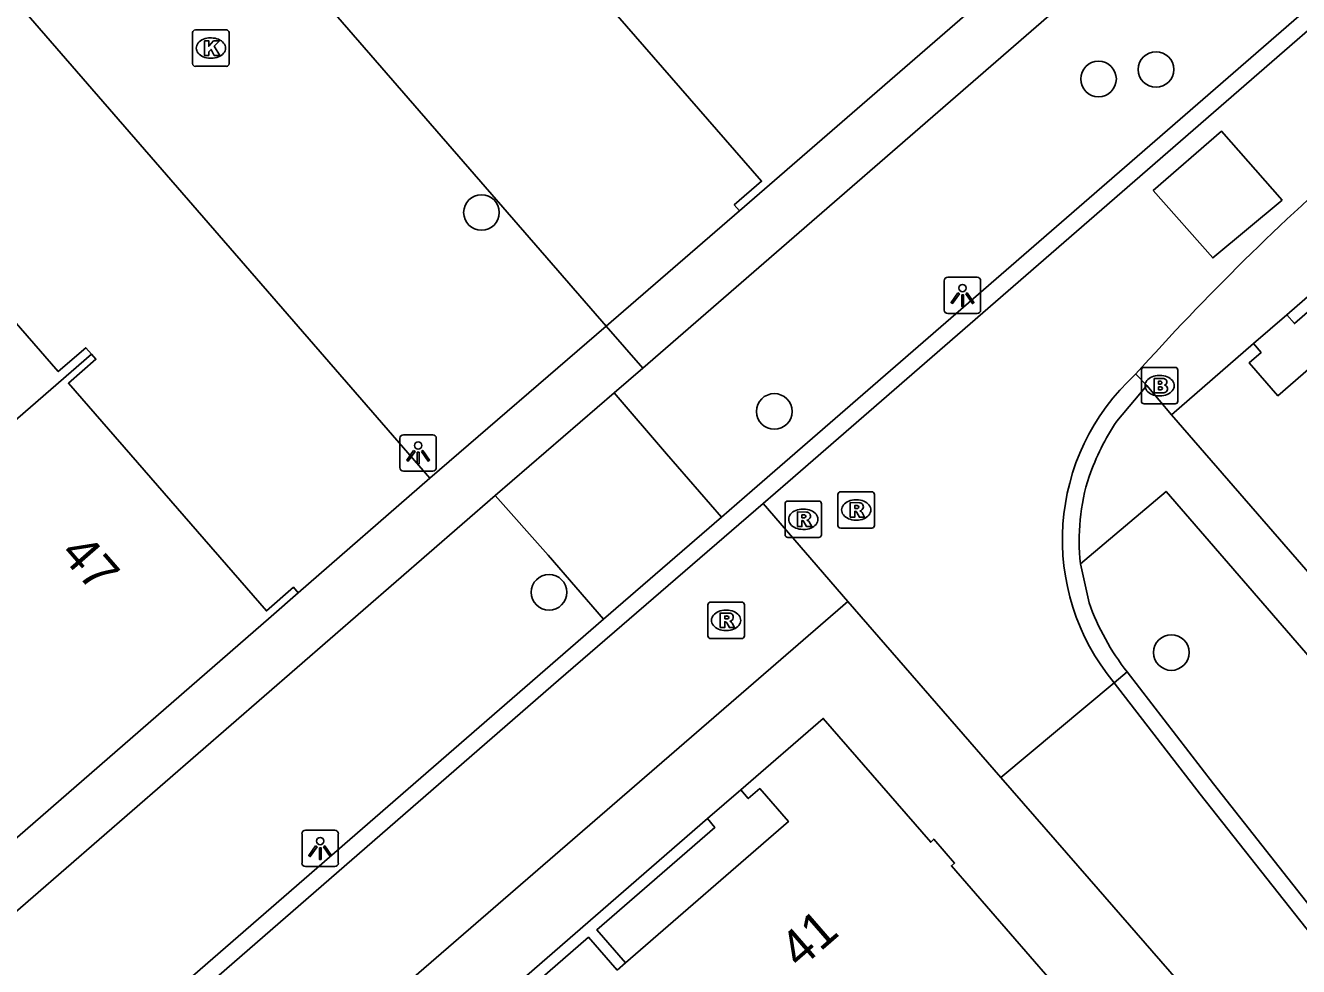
# Model space of a CAD drawing. Extents: x 155888 to 156864, y 383882 to 384671.
# Drawn here: x 156470.82 to 156505.75, y 384184.97 to 384210.79 of the extents above; entities that cross this region are included whole.
import ezdxf

# ---------------------------------------------------------------- set-up
doc = ezdxf.new("R2010")
doc.units = 0
for name, color, linetype in [('IMGEO_Boom', 7, 'Continuous'), ('IMGEO_Brandkraan', 7, 'Continuous'), ('IMGEO_Kolk', 7, 'Continuous'), ('IMGEO_Lichtpunt', 7, 'Continuous'), ('IMGEO_Muur', 7, 'Continuous'), ('IMGEO_Pand', 7, 'Continuous'), ('IMGEO_Pand_nummerreeks', 7, 'Continuous'), ('IMGEO_Rijbaan_lokaal_gesloten', 7, 'Continuous'), ('IMGEO_Rijbaan_lokaal_open', 7, 'Continuous'), ('IMGEO_Rioolput', 7, 'Continuous'), ('IMGEO_Voetpad_open', 7, 'Continuous')]:
    doc.layers.add(name, color=color, linetype=linetype)

msp = doc.modelspace()

# ---------------------------------------------------------------- linework, layer by layer
at = {"layer": 'IMGEO_Boom'}
for centre in [(156500.259, 384209.32), (156501.836, 384209.58), (156483.328, 384205.656), (156491.362, 384200.197), (156485.182, 384195.235), (156502.256, 384193.581)]:
    msp.add_circle(centre, 0.489, dxfattribs=at)
at = {"layer": 'IMGEO_Brandkraan'}
for p, q in [((156501.509, 384201.405), (156502.361, 384201.405)), ((156501.434, 384200.479), (156501.434, 384201.331)), ((156501.922, 384201.185), (156501.947, 384201.185)), ((156502.435, 384201.331), (156502.435, 384200.479)), ((156502.361, 384200.405), (156501.509, 384200.405)), ((156501.945, 384200.625), (156501.92, 384200.625))]:
    msp.add_line(p, q, dxfattribs=at)
for points in [[(156501.509, 384201.405), (156502.361, 384201.405)], [(156501.434, 384200.479), (156501.434, 384201.331)], [(156501.782, 384201.105), (156501.782, 384200.705), (156501.995, 384200.705)], [(156502.013, 384201.105), (156501.782, 384201.105)], [(156502.435, 384201.331), (156502.435, 384200.479)], [(156501.961, 384201.024), (156501.907, 384201.024), (156501.907, 384200.948)], [(156501.907, 384200.948), (156501.96, 384200.948)], [(156501.969, 384200.872), (156501.907, 384200.872), (156501.907, 384200.791)], [(156501.907, 384200.791), (156501.969, 384200.791)], [(156502.361, 384200.405), (156501.509, 384200.405)]]:
    msp.add_lwpolyline(points, dxfattribs=at)
for centre, radius, start, end in [((156501.511, 384201.329), 0.0765, 91.552, 178.448), ((156501.511, 384201.329), 0.0765, 91.552, 178.448), ((156502.359, 384201.329), 0.0765, 1.552, 88.448), ((156502.359, 384201.329), 0.0765, 1.552, 88.448), ((156502.017, 384200.96), 0.145, 59.4692, 91.5367), ((156502.042, 384201.007), 0.0922, 285.5137, 58.1501), ((156501.962, 384200.986), 0.0379, 267.8285, 90.9355), ((156501.97, 384200.831), 0.0404, 269.8759, 90.5077), ((156502.001, 384200.956), 0.251, 268.6676, 293.5347), ((156502.047, 384200.815), 0.105, 301.3115, 78.989), ((156501.511, 384200.481), 0.0765, 181.552, 268.448), ((156501.511, 384200.481), 0.0765, 181.552, 268.448), ((156502.359, 384200.481), 0.0765, 271.552, 358.448), ((156502.359, 384200.481), 0.0765, 271.552, 358.448)]:
    msp.add_arc(centre, radius, start, end, dxfattribs=at)
for centre, major_axis, ratio, start_param, end_param in [((156501.921, 384200.905), (-0.387, 0.002), 0.722429, 4.712389, 7.853982), ((156501.946, 384200.905), (-0.39, 0.002), 0.717154, 1.570796, 4.712389)]:
    msp.add_ellipse(centre, major_axis=major_axis, ratio=ratio, start_param=start_param, end_param=end_param, dxfattribs=at)
at = {"layer": 'IMGEO_Kolk'}
for p, q in [((156475.403, 384209.741), (156475.403, 384210.593)), ((156475.478, 384210.667), (156476.33, 384210.667)), ((156476.404, 384210.593), (156476.404, 384209.741)), ((156475.891, 384210.447), (156475.916, 384210.447)), ((156475.914, 384209.887), (156475.889, 384209.887)), ((156476.33, 384209.667), (156475.478, 384209.667))]:
    msp.add_line(p, q, dxfattribs=at)
for points in [[(156475.403, 384209.741), (156475.403, 384210.593)], [(156475.478, 384210.667), (156476.33, 384210.667)], [(156476.404, 384210.593), (156476.404, 384209.741)], [(156475.724, 384210.367), (156475.847, 384210.367), (156475.847, 384210.216), (156475.977, 384210.367), (156476.141, 384210.367), (156475.995, 384210.216), (156476.148, 384209.967), (156475.996, 384209.967), (156475.911, 384210.131), (156475.847, 384210.064), (156475.847, 384209.967), (156475.724, 384209.967), (156475.724, 384210.367)], [(156476.33, 384209.667), (156475.478, 384209.667)]]:
    msp.add_lwpolyline(points, dxfattribs=at)
for centre, start, end in [((156475.48, 384210.591), 91.552, 178.448), ((156475.48, 384210.591), 91.552, 178.448), ((156476.328, 384210.591), 1.552, 88.448), ((156476.328, 384210.591), 1.552, 88.448), ((156475.48, 384209.743), 181.552, 268.448), ((156475.48, 384209.743), 181.552, 268.448), ((156476.328, 384209.743), 271.552, 358.448), ((156476.328, 384209.743), 271.552, 358.448)]:
    msp.add_arc(centre, 0.0765, start, end, dxfattribs=at)
for centre, major_axis, ratio, start_param, end_param in [((156475.89, 384210.167), (-0.387, 0.002), 0.722429, 4.712389, 7.853982), ((156475.915, 384210.167), (-0.39, 0.002), 0.717154, 1.570796, 4.712389)]:
    msp.add_ellipse(centre, major_axis=major_axis, ratio=ratio, start_param=start_param, end_param=end_param, dxfattribs=at)
at = {"layer": 'IMGEO_Lichtpunt'}
for p, q in [((156496.93, 384203.88), (156496.122, 384203.88)), ((156496.93, 384203.88), (156496.122, 384203.88)), ((156496.028, 384203.785), (156496.028, 384202.978)), ((156496.028, 384203.785), (156496.028, 384202.978)), ((156497.024, 384202.978), (156497.024, 384203.785)), ((156497.024, 384202.978), (156497.024, 384203.785)), ((156496.122, 384202.884), (156496.93, 384202.884)), ((156496.122, 384202.884), (156496.93, 384202.884)), ((156481.092, 384199.463), (156481.092, 384198.656)), ((156481.092, 384199.463), (156481.092, 384198.656)), ((156481.994, 384199.558), (156481.186, 384199.558)), ((156481.994, 384199.558), (156481.186, 384199.558)), ((156482.088, 384198.656), (156482.088, 384199.463)), ((156482.088, 384198.656), (156482.088, 384199.463)), ((156481.186, 384198.562), (156481.994, 384198.562)), ((156481.186, 384198.562), (156481.994, 384198.562)), ((156478.404, 384188.61), (156478.404, 384187.803)), ((156478.404, 384188.61), (156478.404, 384187.803)), ((156479.306, 384188.705), (156478.498, 384188.705)), ((156479.306, 384188.705), (156478.498, 384188.705)), ((156479.4, 384187.803), (156479.4, 384188.61)), ((156479.4, 384187.803), (156479.4, 384188.61)), ((156478.498, 384187.709), (156479.306, 384187.709)), ((156478.498, 384187.709), (156479.306, 384187.709))]:
    msp.add_line(p, q, dxfattribs=at)
for points in [[(156496.402, 384203.449), (156496.441, 384203.421), (156496.253, 384203.159), (156496.215, 384203.186), (156496.402, 384203.449)], [(156496.504, 384203.401), (156496.551, 384203.401), (156496.551, 384203.079), (156496.504, 384203.079), (156496.504, 384203.401)], [(156496.614, 384203.421), (156496.652, 384203.448), (156496.839, 384203.186), (156496.8, 384203.158), (156496.614, 384203.421)], [(156481.466, 384199.127), (156481.505, 384199.099), (156481.317, 384198.837), (156481.279, 384198.864), (156481.466, 384199.127)], [(156481.568, 384199.079), (156481.615, 384199.079), (156481.615, 384198.757), (156481.568, 384198.757), (156481.568, 384199.079)], [(156481.678, 384199.099), (156481.716, 384199.126), (156481.903, 384198.864), (156481.864, 384198.836), (156481.678, 384199.099)], [(156478.778, 384188.274), (156478.817, 384188.246), (156478.629, 384187.984), (156478.591, 384188.011), (156478.778, 384188.274)], [(156478.88, 384188.226), (156478.927, 384188.226), (156478.927, 384187.904), (156478.88, 384187.904), (156478.88, 384188.226)], [(156478.99, 384188.246), (156479.028, 384188.273), (156479.215, 384188.011), (156479.176, 384187.983), (156478.99, 384188.246)]]:
    msp.add_lwpolyline(points, dxfattribs=at)
for centre in [(156496.527, 384203.583), (156481.591, 384199.261), (156478.903, 384188.408)]:
    msp.add_circle(centre, 0.0994, dxfattribs=at)
for centre, start, end in [((156496.122, 384203.785), 90, 180), ((156496.122, 384203.785), 90, 180), ((156496.93, 384203.785), 0, 90), ((156496.93, 384203.785), 0, 90), ((156496.122, 384202.978), 180, 270), ((156496.122, 384202.978), 180, 270), ((156496.93, 384202.978), 270, 0), ((156496.93, 384202.978), 270, 360), ((156481.186, 384199.463), 90, 180), ((156481.186, 384199.463), 90, 180), ((156481.994, 384199.463), 0, 90), ((156481.994, 384199.463), 0, 90), ((156481.186, 384198.656), 180, 270), ((156481.186, 384198.656), 180, 270), ((156481.994, 384198.656), 270, 0), ((156481.994, 384198.656), 270, 360), ((156478.498, 384188.61), 90, 180), ((156478.498, 384188.61), 90, 180), ((156479.306, 384188.61), 0, 90), ((156479.306, 384188.61), 0, 90), ((156478.498, 384187.803), 180, 270), ((156478.498, 384187.803), 180, 270), ((156479.306, 384187.803), 270, 0), ((156479.306, 384187.803), 270, 360)]:
    msp.add_arc(centre, 0.0946, start, end, dxfattribs=at)
at = {"layer": 'IMGEO_Muur'}
for points in [[(156505.425, 384202.851), (156512.123, 384208.672)], [(156509.637, 384204.498), (156508.866, 384205.417), (156505.635, 384202.609), (156505.425, 384202.851)], [(156482.827, 384183.202), (156489.529, 384189.025)], [(156489.529, 384189.025), (156489.735, 384188.784), (156486.493, 384185.969), (156487.278, 384185.064)], [(156487.051, 384184.867), (156486.264, 384185.77), (156483.032, 384182.964), (156482.827, 384183.202)]]:
    msp.add_lwpolyline(points, dxfattribs=at)
at = {"layer": 'IMGEO_Pand'}
for points in [[(156484.691, 384212.264), (156484.827, 384212.107), (156485.582, 384212.763), (156491.013, 384206.514), (156490.264, 384205.866), (156490.404, 384205.705)], [(156490.404, 384205.705), (156498.314, 384212.563)], [(156467.048, 384208.181), (156467.176, 384208.034), (156466.422, 384207.378), (156471.717, 384201.289), (156472.472, 384201.945), (156472.624, 384201.771)], [(156509.637, 384204.498), (156505.18, 384200.628), (156504.393, 384201.534), (156504.718, 384201.816), (156504.508, 384202.058)], [(156472.624, 384201.771), (156459.646, 384190.5)], [(156478.3, 384195.219), (156478.169, 384195.371), (156477.427, 384194.725), (156471.993, 384200.972), (156472.748, 384201.629), (156472.624, 384201.771)], [(156504.508, 384202.058), (156502.257, 384200.103)], [(156502.257, 384200.103), (156512.362, 384188.479)], [(156470.389, 384188.333), (156477.559, 384194.574), (156478.3, 384195.219)], [(156502.801, 384180.137), (156500, 384183.372), (156496.224, 384187.732), (156496.307, 384187.804), (156495.736, 384188.462), (156495.656, 384188.378), (156492.708, 384191.775), (156490.444, 384189.81)], [(156490.444, 384189.81), (156490.646, 384189.575), (156490.962, 384189.85), (156491.748, 384188.945), (156487.278, 384185.064)], [(156487.278, 384185.064), (156487.051, 384184.867)]]:
    msp.add_lwpolyline(points, dxfattribs=at)
at = {"layer": 'IMGEO_Rijbaan_lokaal_gesloten'}
for points in [[(156547.776, 384246.974), (156547.528, 384246.758), (156546.36, 384245.735), (156545.502, 384244.98), (156537.299, 384237.854), (156529.516, 384231.093), (156523.251, 384225.637), (156500, 384205.436), (156491.733, 384198.254), (156491.055, 384197.674)], [(156491.055, 384197.674), (156493.377, 384194.981)], [(156493.377, 384194.981), (156497.577, 384190.155)], [(156497.577, 384190.155), (156500.691, 384192.754)], [(156529.278, 384160.045), (156525.433, 384163.778), (156523.049, 384166.283), (156519.991, 384169.766), (156513.12, 384177.689), (156508.974, 384182.475), (156505.949, 384186.025), (156503.045, 384189.697), (156500.691, 384192.754)], [(156497.577, 384190.155), (156500, 384187.371), (156525.991, 384157.507)]]:
    msp.add_lwpolyline(points, dxfattribs=at)
for centre, radius, start, end in [((156550.862, 384156.992), 66.441, 130.81095, 138.27039), ((156505.394, 384196.679), 6.126, 132.218, 219.8456)]:
    msp.add_arc(centre, radius, start, end, dxfattribs=at)
at = {"layer": 'IMGEO_Rijbaan_lokaal_open'}
for points in [[(156486.746, 384202.533), (156453.061, 384241.329)], [(156448.242, 384237.145), (156481.913, 384198.365)], [(156522.949, 384225.984), (156500, 384206.046), (156490.753, 384198.024), (156489.913, 384197.295)], [(156505.293, 384205.994), (156503.395, 384204.412), (156501.76, 384206.259), (156503.631, 384207.891), (156505.293, 384205.994)], [(156481.913, 384198.365), (156486.746, 384202.533)], [(156486.972, 384200.71), (156483.706, 384197.89)], [(156489.913, 384197.295), (156488.402, 384199.038), (156486.972, 384200.71)], [(156483.706, 384197.89), (156485.158, 384196.251), (156486.678, 384194.498)], [(156491.055, 384197.674), (156485.441, 384192.82), (156474.104, 384182.967), (156471.543, 384180.768)], [(156486.678, 384194.498), (156489.913, 384197.295)], [(156473.853, 384178.078), (156491.406, 384193.275), (156493.377, 384194.981)], [(156486.678, 384194.498), (156473.803, 384183.315), (156471.243, 384181.117)]]:
    msp.add_lwpolyline(points, dxfattribs=at)
at = {"layer": 'IMGEO_Rioolput'}
for p, q in [((156493.109, 384197.068), (156493.109, 384197.92)), ((156493.184, 384197.994), (156494.036, 384197.994)), ((156494.11, 384197.92), (156494.11, 384197.068)), ((156491.658, 384196.813), (156491.658, 384197.665)), ((156491.733, 384197.739), (156492.585, 384197.739)), ((156492.659, 384197.665), (156492.659, 384196.813)), ((156493.597, 384197.774), (156493.622, 384197.774)), ((156492.146, 384197.519), (156492.171, 384197.519)), ((156493.62, 384197.214), (156493.595, 384197.214)), ((156492.169, 384196.959), (156492.144, 384196.959)), ((156494.036, 384196.994), (156493.184, 384196.994)), ((156492.585, 384196.739), (156491.733, 384196.739)), ((156489.54, 384194.039), (156489.54, 384194.891)), ((156489.615, 384194.965), (156490.467, 384194.965)), ((156490.541, 384194.891), (156490.541, 384194.039)), ((156490.028, 384194.745), (156490.053, 384194.745)), ((156490.051, 384194.185), (156490.026, 384194.185)), ((156490.467, 384193.965), (156489.615, 384193.965))]:
    msp.add_line(p, q, dxfattribs=at)
for points in [[(156493.109, 384197.068), (156493.109, 384197.92)], [(156493.184, 384197.994), (156494.036, 384197.994)], [(156494.11, 384197.92), (156494.11, 384197.068)], [(156491.658, 384196.813), (156491.658, 384197.665)], [(156491.733, 384197.739), (156492.585, 384197.739)], [(156492.659, 384197.665), (156492.659, 384196.813)], [(156493.698, 384197.692), (156493.446, 384197.694), (156493.446, 384197.294)], [(156493.624, 384197.613), (156493.57, 384197.613), (156493.57, 384197.532)], [(156492.247, 384197.437), (156491.995, 384197.439), (156491.995, 384197.039)], [(156491.995, 384197.039), (156492.119, 384197.039), (156492.119, 384197.201), (156492.13, 384197.201)], [(156492.173, 384197.358), (156492.119, 384197.358), (156492.119, 384197.277)], [(156492.119, 384197.277), (156492.171, 384197.277)], [(156493.446, 384197.294), (156493.57, 384197.294), (156493.57, 384197.456), (156493.581, 384197.456)], [(156493.57, 384197.532), (156493.622, 384197.532)], [(156493.628, 384197.427), (156493.699, 384197.294), (156493.839, 384197.294), (156493.774, 384197.42)], [(156492.177, 384197.172), (156492.248, 384197.039), (156492.388, 384197.039), (156492.323, 384197.165)], [(156494.036, 384196.994), (156493.184, 384196.994)], [(156492.585, 384196.739), (156491.733, 384196.739)], [(156489.54, 384194.039), (156489.54, 384194.891)], [(156489.615, 384194.965), (156490.467, 384194.965)], [(156490.541, 384194.891), (156490.541, 384194.039)], [(156490.129, 384194.663), (156489.877, 384194.665), (156489.877, 384194.265)], [(156489.877, 384194.265), (156490.001, 384194.265), (156490.001, 384194.427), (156490.012, 384194.427)], [(156490.055, 384194.584), (156490.001, 384194.584), (156490.001, 384194.503)], [(156490.001, 384194.503), (156490.053, 384194.503)], [(156490.059, 384194.398), (156490.13, 384194.265), (156490.27, 384194.265), (156490.205, 384194.391)], [(156490.467, 384193.965), (156489.615, 384193.965)]]:
    msp.add_lwpolyline(points, dxfattribs=at)
for centre, radius, start, end in [((156493.186, 384197.918), 0.0765, 91.552, 178.448), ((156493.186, 384197.918), 0.0765, 91.552, 178.448), ((156494.034, 384197.918), 0.0765, 1.552, 88.448), ((156494.034, 384197.918), 0.0765, 1.552, 88.448), ((156491.735, 384197.663), 0.0765, 91.552, 178.448), ((156491.735, 384197.663), 0.0765, 91.552, 178.448), ((156492.583, 384197.663), 0.0765, 1.552, 88.448), ((156492.583, 384197.663), 0.0765, 1.552, 88.448), ((156493.63, 384197.517), 0.0964, 77.0061, 93.1865), ((156493.644, 384197.574), 0.0378, 276.6634, 79.6772), ((156493.697, 384197.582), 0.109, 350.3612, 89.416), ((156493.695, 384197.582), 0.112, 277.5842, 350.9817), ((156492.129, 384197.148), 0.0533, 26.0293, 88.6989), ((156492.155, 384197.466), 0.19, 274.7715, 282.9687), ((156492.179, 384197.262), 0.0964, 77.0061, 93.1865), ((156492.193, 384197.319), 0.0378, 276.6634, 79.6772), ((156492.246, 384197.327), 0.109, 350.3612, 89.416), ((156492.244, 384197.327), 0.112, 277.5842, 350.9817), ((156492.228, 384197.112), 0.108, 29.5134, 73.7905), ((156493.58, 384197.403), 0.0533, 26.0293, 88.6989), ((156493.606, 384197.721), 0.19, 274.7715, 282.9687), ((156493.679, 384197.367), 0.108, 29.5134, 73.7905), ((156493.186, 384197.07), 0.0765, 181.552, 268.448), ((156493.186, 384197.07), 0.0765, 181.552, 268.448), ((156494.034, 384197.07), 0.0765, 271.552, 358.448), ((156494.034, 384197.07), 0.0765, 271.552, 358.448), ((156491.735, 384196.815), 0.0765, 181.552, 268.448), ((156491.735, 384196.815), 0.0765, 181.552, 268.448), ((156492.583, 384196.815), 0.0765, 271.552, 358.448), ((156492.583, 384196.815), 0.0765, 271.552, 358.448), ((156489.617, 384194.889), 0.0765, 91.552, 178.448), ((156489.617, 384194.889), 0.0765, 91.552, 178.448), ((156490.465, 384194.889), 0.0765, 1.552, 88.448), ((156490.465, 384194.889), 0.0765, 1.552, 88.448), ((156490.011, 384194.374), 0.0533, 26.0293, 88.6989), ((156490.037, 384194.692), 0.19, 274.7715, 282.9687), ((156490.061, 384194.488), 0.0964, 77.0061, 93.1865), ((156490.075, 384194.545), 0.0378, 276.6634, 79.6772), ((156490.128, 384194.553), 0.109, 350.3612, 89.416), ((156490.126, 384194.553), 0.112, 277.5842, 350.9817), ((156490.11, 384194.338), 0.108, 29.5134, 73.7905), ((156489.617, 384194.041), 0.0765, 181.552, 268.448), ((156489.617, 384194.041), 0.0765, 181.552, 268.448), ((156490.465, 384194.041), 0.0765, 271.552, 358.448), ((156490.465, 384194.041), 0.0765, 271.552, 358.448)]:
    msp.add_arc(centre, radius, start, end, dxfattribs=at)
for centre, major_axis, ratio, start_param, end_param in [((156493.596, 384197.494), (-0.387, 0.002), 0.722429, 4.712389, 7.853982), ((156493.621, 384197.494), (-0.39, 0.002), 0.717154, 1.570796, 4.712389), ((156492.145, 384197.239), (-0.387, 0.002), 0.722429, 4.712389, 7.853982), ((156492.17, 384197.239), (-0.39, 0.002), 0.717154, 1.570796, 4.712389), ((156490.027, 384194.465), (-0.387, 0.002), 0.722429, 4.712389, 7.853982), ((156490.052, 384194.465), (-0.39, 0.002), 0.717154, 1.570796, 4.712389)]:
    msp.add_ellipse(centre, major_axis=major_axis, ratio=ratio, start_param=start_param, end_param=end_param, dxfattribs=at)
at = {"layer": 'IMGEO_Voetpad_open'}
for points in [[(156521.497, 384230.686), (156500, 384212.021), (156487.753, 384201.388)], [(156486.746, 384202.533), (156490.404, 384205.705)], [(156504.508, 384202.058), (156505.425, 384202.851)], [(156486.746, 384202.533), (156487.753, 384201.388)], [(156487.753, 384201.388), (156486.972, 384200.71)], [(156501.278, 384201.216), (156501.585, 384200.905)], [(156501.585, 384200.905), (156500.757, 384199.93)], [(156501.585, 384200.905), (156502.257, 384200.103)], [(156478.3, 384195.219), (156481.913, 384198.365)], [(156468.306, 384184.517), (156483.706, 384197.89)], [(156506.306, 384186.314), (156507.903, 384187.617), (156509.172, 384186.12), (156511.017, 384187.715), (156502.111, 384198.002), (156500, 384196.217), (156499.766, 384196.019)], [(156499.766, 384196.019), (156500, 384194.946)], [(156500.691, 384192.754), (156501.045, 384193.049)], [(156501.045, 384193.049), (156503.409, 384189.978), (156506.306, 384186.314)], [(156489.529, 384189.025), (156490.444, 384189.81)]]:
    msp.add_lwpolyline(points, dxfattribs=at)
for centre, radius, start, end in [((156506.684, 384196.03), 7.095, 146.6529, 160.3981), ((156505.402, 384196.674), 5.674, 162.1881, 186.6327), ((156506.446, 384197.26), 6.849, 199.7514, 217.9467)]:
    msp.add_arc(centre, radius, start, end, dxfattribs=at)

# ---------------------------------------------------------------- texts
at = {"layer": 'IMGEO_Pand_nummerreeks'}
for s, rotation, p in [('47', 311.0175, (156471.733, 384196.275)), ('41', 40.9877, (156492.062, 384184.873))]:
    msp.add_text(s, height=1, rotation=rotation, dxfattribs=at).set_placement(p)

doc.saveas('drawing.dxf')
